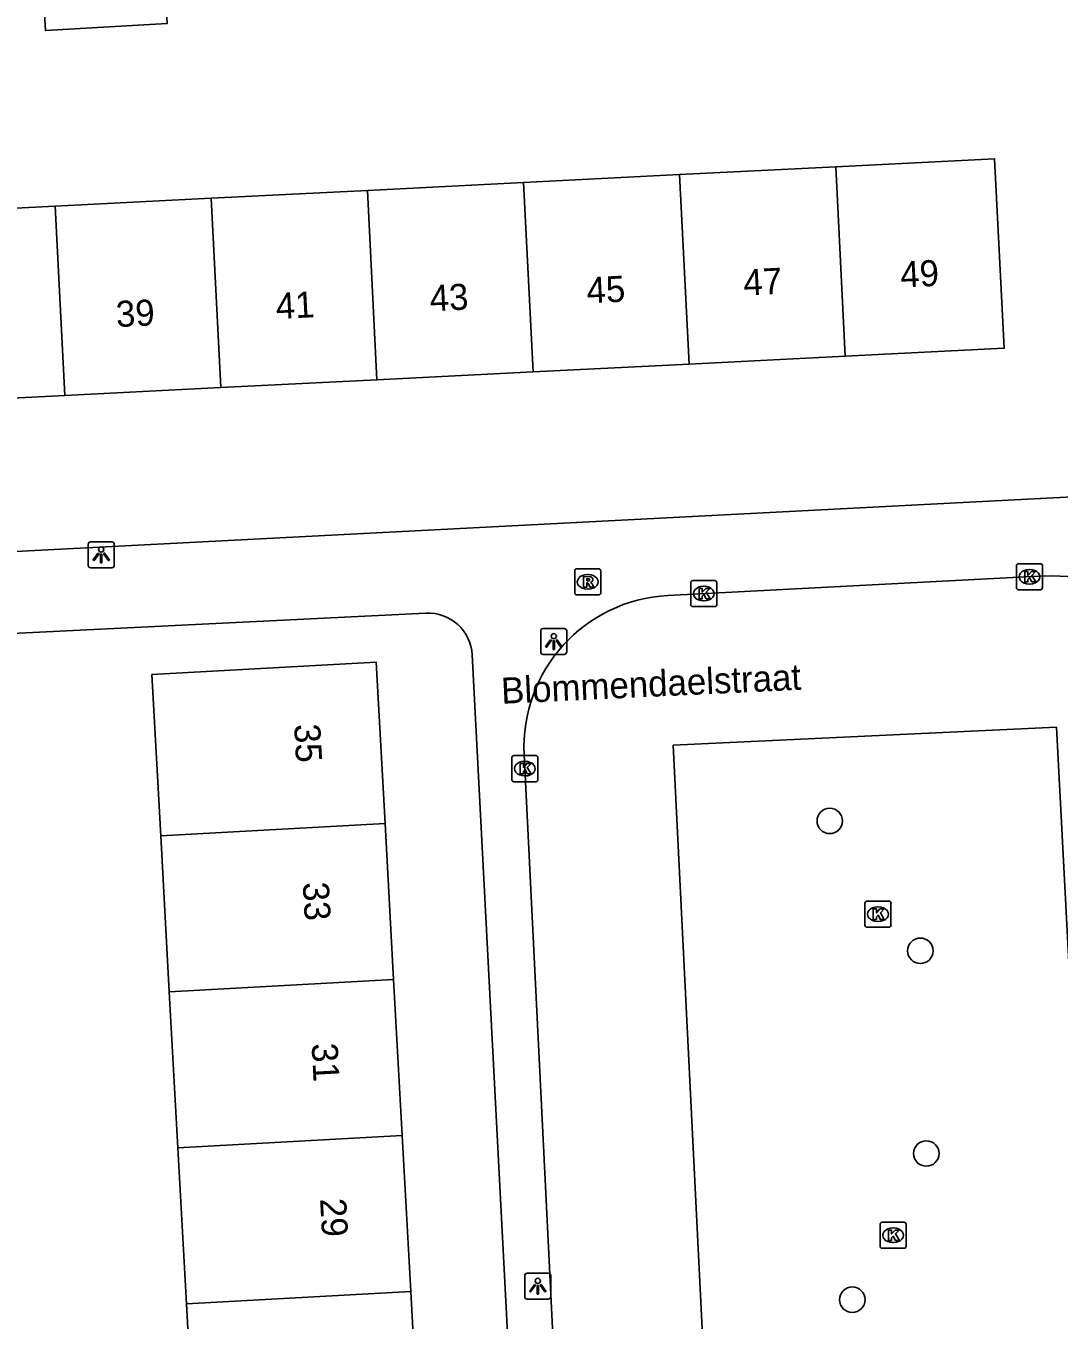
# Model space of a CAD drawing. Extents: x 160557 to 161245, y 385330 to 386505.
# Drawn here: x 161032.93 to 161072.59, y 385418.6 to 385468.29 of the extents above; entities that cross this region are included whole.
import ezdxf

# ---------------------------------------------------------------- set-up
doc = ezdxf.new("R2010")
doc.units = 0
for name, color, linetype in [('IMGEO_Boom', 7, 'Continuous'), ('IMGEO_Kolk', 7, 'Continuous'), ('IMGEO_Lichtpunt', 7, 'Continuous'), ('IMGEO_Openbare_ruimte_label', 7, 'Continuous'), ('IMGEO_Pand', 7, 'Continuous'), ('IMGEO_Pand_nummerreeks', 7, 'Continuous'), ('IMGEO_Rijbaan_lokaal_open', 7, 'Continuous'), ('IMGEO_Rioolput', 7, 'Continuous'), ('IMGEO_Voetpad_open', 7, 'Continuous')]:
    doc.layers.add(name, color=color, linetype=linetype)

msp = doc.modelspace()

# ---------------------------------------------------------------- linework, layer by layer
at = {"layer": 'IMGEO_Boom'}
for centre in [(161063.785, 385437.768), (161067.263, 385432.783), (161067.492, 385425.001), (161064.651, 385419.387)]:
    msp.add_circle(centre, 0.489, dxfattribs=at)
at = {"layer": 'IMGEO_Kolk'}
for p, q in [((161071.025, 385447.642), (161071.877, 385447.642)), ((161070.95, 385446.716), (161070.95, 385447.568)), ((161071.438, 385447.422), (161071.463, 385447.422)), ((161071.951, 385447.568), (161071.951, 385446.716)), ((161058.45, 385446.069), (161058.45, 385446.921)), ((161058.525, 385446.995), (161059.377, 385446.995)), ((161058.938, 385446.775), (161058.963, 385446.775)), ((161059.451, 385446.921), (161059.451, 385446.069)), ((161071.877, 385446.642), (161071.025, 385446.642)), ((161071.461, 385446.862), (161071.436, 385446.862)), ((161058.961, 385446.215), (161058.936, 385446.215)), ((161059.377, 385445.995), (161058.525, 385445.995)), ((161051.581, 385439.349), (161051.581, 385440.201)), ((161051.656, 385440.275), (161052.508, 385440.275)), ((161052.582, 385440.201), (161052.582, 385439.349)), ((161052.069, 385440.055), (161052.094, 385440.055)), ((161052.508, 385439.275), (161051.656, 385439.275)), ((161052.092, 385439.495), (161052.067, 385439.495)), ((161065.135, 385433.762), (161065.135, 385434.614)), ((161065.21, 385434.688), (161066.062, 385434.688)), ((161065.623, 385434.468), (161065.648, 385434.468)), ((161066.136, 385434.614), (161066.136, 385433.762)), ((161065.646, 385433.908), (161065.621, 385433.908)), ((161066.062, 385433.688), (161065.21, 385433.688)), ((161065.717, 385421.436), (161065.717, 385422.288)), ((161065.792, 385422.362), (161066.644, 385422.362)), ((161066.718, 385422.288), (161066.718, 385421.436)), ((161066.205, 385422.142), (161066.23, 385422.142)), ((161066.644, 385421.362), (161065.792, 385421.362)), ((161066.228, 385421.582), (161066.203, 385421.582))]:
    msp.add_line(p, q, dxfattribs=at)
for points in [[(161071.025, 385447.642), (161071.877, 385447.642)], [(161070.95, 385446.716), (161070.95, 385447.568)], [(161071.271, 385447.342), (161071.394, 385447.342), (161071.394, 385447.191), (161071.524, 385447.342), (161071.688, 385447.342), (161071.542, 385447.191), (161071.695, 385446.942), (161071.543, 385446.942), (161071.458, 385447.106), (161071.394, 385447.039), (161071.394, 385446.942), (161071.271, 385446.942), (161071.271, 385447.342)], [(161071.951, 385447.568), (161071.951, 385446.716)], [(161058.45, 385446.069), (161058.45, 385446.921)], [(161058.525, 385446.995), (161059.377, 385446.995)], [(161058.771, 385446.695), (161058.894, 385446.695), (161058.894, 385446.544), (161059.024, 385446.695), (161059.188, 385446.695), (161059.042, 385446.544), (161059.195, 385446.295), (161059.043, 385446.295), (161058.958, 385446.459), (161058.894, 385446.392), (161058.894, 385446.295), (161058.771, 385446.295), (161058.771, 385446.695)], [(161059.451, 385446.921), (161059.451, 385446.069)], [(161071.877, 385446.642), (161071.025, 385446.642)], [(161059.377, 385445.995), (161058.525, 385445.995)], [(161051.581, 385439.349), (161051.581, 385440.201)], [(161051.656, 385440.275), (161052.508, 385440.275)], [(161052.582, 385440.201), (161052.582, 385439.349)], [(161051.902, 385439.975), (161052.025, 385439.975), (161052.025, 385439.824), (161052.155, 385439.975), (161052.319, 385439.975), (161052.173, 385439.824), (161052.326, 385439.575), (161052.174, 385439.575), (161052.089, 385439.739), (161052.025, 385439.672), (161052.025, 385439.575), (161051.902, 385439.575), (161051.902, 385439.975)], [(161052.508, 385439.275), (161051.656, 385439.275)], [(161065.135, 385433.762), (161065.135, 385434.614)], [(161065.21, 385434.688), (161066.062, 385434.688)], [(161065.456, 385434.388), (161065.579, 385434.388), (161065.579, 385434.237), (161065.709, 385434.388), (161065.873, 385434.388), (161065.727, 385434.237), (161065.88, 385433.988), (161065.728, 385433.988), (161065.643, 385434.152), (161065.579, 385434.085), (161065.579, 385433.988), (161065.456, 385433.988), (161065.456, 385434.388)], [(161066.136, 385434.614), (161066.136, 385433.762)], [(161066.062, 385433.688), (161065.21, 385433.688)], [(161065.717, 385421.436), (161065.717, 385422.288)], [(161065.792, 385422.362), (161066.644, 385422.362)], [(161066.718, 385422.288), (161066.718, 385421.436)], [(161066.038, 385422.062), (161066.161, 385422.062), (161066.161, 385421.911), (161066.291, 385422.062), (161066.455, 385422.062), (161066.309, 385421.911), (161066.462, 385421.662), (161066.31, 385421.662), (161066.225, 385421.826), (161066.161, 385421.759), (161066.161, 385421.662), (161066.038, 385421.662), (161066.038, 385422.062)], [(161066.644, 385421.362), (161065.792, 385421.362)]]:
    msp.add_lwpolyline(points, dxfattribs=at)
for centre, start, end in [((161071.027, 385447.566), 91.552, 178.448), ((161071.027, 385447.566), 91.552, 178.448), ((161071.875, 385447.566), 1.552, 88.448), ((161071.875, 385447.566), 1.552, 88.448), ((161058.527, 385446.919), 91.552, 178.448), ((161058.527, 385446.919), 91.552, 178.448), ((161059.375, 385446.919), 1.552, 88.448), ((161059.375, 385446.919), 1.552, 88.448), ((161071.027, 385446.718), 181.552, 268.448), ((161071.027, 385446.718), 181.552, 268.448), ((161071.875, 385446.718), 271.552, 358.448), ((161071.875, 385446.718), 271.552, 358.448), ((161058.527, 385446.071), 181.552, 268.448), ((161058.527, 385446.071), 181.552, 268.448), ((161059.375, 385446.071), 271.552, 358.448), ((161059.375, 385446.071), 271.552, 358.448), ((161051.658, 385440.199), 91.552, 178.448), ((161051.658, 385440.199), 91.552, 178.448), ((161052.506, 385440.199), 1.552, 88.448), ((161052.506, 385440.199), 1.552, 88.448), ((161051.658, 385439.351), 181.552, 268.448), ((161051.658, 385439.351), 181.552, 268.448), ((161052.506, 385439.351), 271.552, 358.448), ((161052.506, 385439.351), 271.552, 358.448), ((161065.212, 385434.612), 91.552, 178.448), ((161065.212, 385434.612), 91.552, 178.448), ((161066.06, 385434.612), 1.552, 88.448), ((161066.06, 385434.612), 1.552, 88.448), ((161065.212, 385433.764), 181.552, 268.448), ((161065.212, 385433.764), 181.552, 268.448), ((161066.06, 385433.764), 271.552, 358.448), ((161066.06, 385433.764), 271.552, 358.448), ((161065.794, 385422.286), 91.552, 178.448), ((161065.794, 385422.286), 91.552, 178.448), ((161066.642, 385422.286), 1.552, 88.448), ((161066.642, 385422.286), 1.552, 88.448), ((161065.794, 385421.438), 181.552, 268.448), ((161065.794, 385421.438), 181.552, 268.448), ((161066.642, 385421.438), 271.552, 358.448), ((161066.642, 385421.438), 271.552, 358.448)]:
    msp.add_arc(centre, 0.0765, start, end, dxfattribs=at)
for centre, major_axis, ratio, start_param, end_param in [((161071.437, 385447.142), (-0.387, 0.002), 0.722429, 4.712389, 7.853982), ((161071.462, 385447.142), (-0.39, 0.002), 0.717154, 1.570796, 4.712389), ((161058.937, 385446.495), (-0.387, 0.002), 0.722429, 4.712389, 7.853982), ((161058.962, 385446.495), (-0.39, 0.002), 0.717154, 1.570796, 4.712389), ((161052.068, 385439.775), (-0.387, 0.002), 0.722429, 4.712389, 7.853982), ((161052.093, 385439.775), (-0.39, 0.002), 0.717154, 1.570796, 4.712389), ((161065.622, 385434.188), (-0.387, 0.002), 0.722429, 4.712389, 7.853982), ((161065.647, 385434.188), (-0.39, 0.002), 0.717154, 1.570796, 4.712389), ((161066.204, 385421.862), (-0.387, 0.002), 0.722429, 4.712389, 7.853982), ((161066.229, 385421.862), (-0.39, 0.002), 0.717154, 1.570796, 4.712389)]:
    msp.add_ellipse(centre, major_axis=major_axis, ratio=ratio, start_param=start_param, end_param=end_param, dxfattribs=at)
at = {"layer": 'IMGEO_Lichtpunt'}
for p, q in [((161035.323, 385448.387), (161035.323, 385447.58)), ((161035.323, 385448.387), (161035.323, 385447.58)), ((161036.225, 385448.482), (161035.417, 385448.482)), ((161036.225, 385448.482), (161035.417, 385448.482)), ((161036.319, 385447.58), (161036.319, 385448.387)), ((161036.319, 385447.58), (161036.319, 385448.387)), ((161035.417, 385447.486), (161036.225, 385447.486)), ((161035.417, 385447.486), (161036.225, 385447.486)), ((161053.594, 385445.156), (161052.786, 385445.156)), ((161053.594, 385445.156), (161052.786, 385445.156)), ((161052.692, 385445.061), (161052.692, 385444.254)), ((161052.692, 385445.061), (161052.692, 385444.254)), ((161053.688, 385444.254), (161053.688, 385445.061)), ((161053.688, 385444.254), (161053.688, 385445.061)), ((161052.786, 385444.16), (161053.594, 385444.16)), ((161052.786, 385444.16), (161053.594, 385444.16)), ((161052.08, 385420.312), (161052.08, 385419.505)), ((161052.08, 385420.312), (161052.08, 385419.505)), ((161052.982, 385420.407), (161052.174, 385420.407)), ((161052.982, 385420.407), (161052.174, 385420.407)), ((161053.076, 385419.505), (161053.076, 385420.312)), ((161053.076, 385419.505), (161053.076, 385420.312)), ((161052.174, 385419.411), (161052.982, 385419.411)), ((161052.174, 385419.411), (161052.982, 385419.411))]:
    msp.add_line(p, q, dxfattribs=at)
for points in [[(161035.697, 385448.051), (161035.736, 385448.023), (161035.548, 385447.761), (161035.51, 385447.788), (161035.697, 385448.051)], [(161035.799, 385448.003), (161035.846, 385448.003), (161035.846, 385447.681), (161035.799, 385447.681), (161035.799, 385448.003)], [(161035.909, 385448.023), (161035.947, 385448.05), (161036.134, 385447.788), (161036.095, 385447.76), (161035.909, 385448.023)], [(161053.066, 385444.725), (161053.105, 385444.697), (161052.917, 385444.435), (161052.879, 385444.462), (161053.066, 385444.725)], [(161053.168, 385444.677), (161053.215, 385444.677), (161053.215, 385444.355), (161053.168, 385444.355), (161053.168, 385444.677)], [(161053.278, 385444.697), (161053.316, 385444.724), (161053.503, 385444.462), (161053.464, 385444.434), (161053.278, 385444.697)], [(161052.454, 385419.976), (161052.493, 385419.948), (161052.305, 385419.686), (161052.267, 385419.713), (161052.454, 385419.976)], [(161052.556, 385419.928), (161052.603, 385419.928), (161052.603, 385419.606), (161052.556, 385419.606), (161052.556, 385419.928)], [(161052.666, 385419.948), (161052.704, 385419.975), (161052.891, 385419.713), (161052.852, 385419.685), (161052.666, 385419.948)]]:
    msp.add_lwpolyline(points, dxfattribs=at)
for centre in [(161035.822, 385448.185), (161053.191, 385444.859), (161052.579, 385420.11)]:
    msp.add_circle(centre, 0.0994, dxfattribs=at)
for centre, start, end in [((161035.417, 385448.387), 90, 180), ((161035.417, 385448.387), 90, 180), ((161036.225, 385448.387), 0, 90), ((161036.225, 385448.387), 0, 90), ((161035.417, 385447.58), 180, 270), ((161035.417, 385447.58), 180, 270), ((161036.225, 385447.58), 270, 0), ((161036.225, 385447.58), 270, 360), ((161052.786, 385445.061), 90, 180), ((161052.786, 385445.061), 90, 180), ((161053.594, 385445.061), 0, 90), ((161053.594, 385445.061), 0, 90), ((161052.786, 385444.254), 180, 270), ((161052.786, 385444.254), 180, 270), ((161053.594, 385444.254), 270, 0), ((161053.594, 385444.254), 270, 360), ((161052.174, 385420.312), 90, 180), ((161052.174, 385420.312), 90, 180), ((161052.982, 385420.312), 0, 90), ((161052.982, 385420.312), 0, 90), ((161052.174, 385419.505), 180, 270), ((161052.174, 385419.505), 180, 270), ((161052.982, 385419.505), 270, 0), ((161052.982, 385419.505), 270, 360)]:
    msp.add_arc(centre, 0.0946, start, end, dxfattribs=at)
at = {"layer": 'IMGEO_Pand'}
for points in [[(161038.209, 385470.94), (161038.357, 385468.383), (161033.677, 385468.112), (161033.529, 385470.669)], [(161064.382, 385455.609), (161070.476, 385455.916), (161070.11, 385463.187), (161064.016, 385462.88)], [(161052.032, 385462.276), (161058.024, 385462.578)], [(161064.016, 385462.88), (161058.024, 385462.578)], [(161058.024, 385462.578), (161058.39, 385455.307)], [(161064.016, 385462.88), (161064.382, 385455.609)], [(161052.032, 385462.276), (161046.039, 385461.974)], [(161052.398, 385455.005), (161052.032, 385462.276)], [(161040.047, 385461.673), (161034.054, 385461.371)], [(161040.047, 385461.673), (161046.039, 385461.974)], [(161040.413, 385454.402), (161040.047, 385461.673)], [(161046.039, 385461.974), (161046.405, 385454.703)], [(161034.054, 385461.371), (161027.965, 385461.064)], [(161034.42, 385454.1), (161034.054, 385461.371)], [(161058.39, 385455.307), (161064.382, 385455.609)], [(161058.39, 385455.307), (161052.398, 385455.005)], [(161046.405, 385454.703), (161040.413, 385454.402)], [(161046.405, 385454.703), (161052.398, 385455.005)], [(161028.331, 385453.793), (161034.42, 385454.1)], [(161034.42, 385454.1), (161040.413, 385454.402)], [(161038.107, 385437.2), (161037.768, 385443.389), (161046.378, 385443.86), (161046.716, 385437.671)], [(161038.107, 385437.2), (161046.716, 385437.671)], [(161038.434, 385431.209), (161038.107, 385437.2)], [(161046.716, 385437.671), (161047.044, 385431.68)], [(161038.434, 385431.209), (161047.044, 385431.68)], [(161047.044, 385431.68), (161047.372, 385425.688)], [(161038.762, 385425.217), (161038.434, 385431.209)], [(161047.372, 385425.688), (161038.762, 385425.217)], [(161047.372, 385425.688), (161047.7, 385419.697)], [(161039.09, 385419.226), (161038.762, 385425.217)], [(161047.7, 385419.697), (161048.038, 385413.509), (161039.428, 385413.039), (161039.09, 385419.226)], [(161039.09, 385419.226), (161047.7, 385419.697)]]:
    msp.add_lwpolyline(points, dxfattribs=at)
at = {"layer": 'IMGEO_Rijbaan_lokaal_open'}
for points in [[(161057.575, 385446.422), (161072.038, 385447.171)], [(161072.491, 385441.37), (161057.78, 385440.68), (161059.018, 385415.696), (161073.778, 385416.7), (161072.491, 385441.37)], [(161053.28, 385415.442), (161052.056, 385440.315)]]:
    msp.add_lwpolyline(points, dxfattribs=at)
for centre, radius, start, end in [((161072.311, 385441.408), 5.769, 3.2282, 92.7104), ((161057.876, 385440.603), 5.827, 92.9602, 182.8305)]:
    msp.add_arc(centre, radius, start, end, dxfattribs=at)
at = {"layer": 'IMGEO_Rioolput'}
for p, q in [((161053.996, 385446.52), (161053.996, 385447.372)), ((161054.071, 385447.446), (161054.923, 385447.446)), ((161054.484, 385447.226), (161054.509, 385447.226)), ((161054.997, 385447.372), (161054.997, 385446.52)), ((161054.507, 385446.666), (161054.482, 385446.666)), ((161054.923, 385446.446), (161054.071, 385446.446))]:
    msp.add_line(p, q, dxfattribs=at)
for points in [[(161053.996, 385446.52), (161053.996, 385447.372)], [(161054.071, 385447.446), (161054.923, 385447.446)], [(161054.585, 385447.144), (161054.333, 385447.146), (161054.333, 385446.746)], [(161054.997, 385447.372), (161054.997, 385446.52)], [(161054.333, 385446.746), (161054.457, 385446.746), (161054.457, 385446.908), (161054.468, 385446.908)], [(161054.511, 385447.065), (161054.457, 385447.065), (161054.457, 385446.984)], [(161054.457, 385446.984), (161054.509, 385446.984)], [(161054.515, 385446.879), (161054.586, 385446.746), (161054.726, 385446.746), (161054.661, 385446.872)], [(161054.923, 385446.446), (161054.071, 385446.446)]]:
    msp.add_lwpolyline(points, dxfattribs=at)
for centre, radius, start, end in [((161054.073, 385447.37), 0.0765, 91.552, 178.448), ((161054.073, 385447.37), 0.0765, 91.552, 178.448), ((161054.584, 385447.034), 0.109, 350.3612, 89.416), ((161054.921, 385447.37), 0.0765, 1.552, 88.448), ((161054.921, 385447.37), 0.0765, 1.552, 88.448), ((161054.467, 385446.855), 0.0533, 26.0293, 88.6989), ((161054.493, 385447.173), 0.19, 274.7715, 282.9687), ((161054.517, 385446.969), 0.0964, 77.0061, 93.1865), ((161054.531, 385447.026), 0.0378, 276.6634, 79.6772), ((161054.582, 385447.034), 0.112, 277.5842, 350.9817), ((161054.566, 385446.819), 0.108, 29.5134, 73.7905), ((161054.073, 385446.522), 0.0765, 181.552, 268.448), ((161054.073, 385446.522), 0.0765, 181.552, 268.448), ((161054.921, 385446.522), 0.0765, 271.552, 358.448), ((161054.921, 385446.522), 0.0765, 271.552, 358.448)]:
    msp.add_arc(centre, radius, start, end, dxfattribs=at)
for centre, major_axis, ratio, start_param, end_param in [((161054.483, 385446.946), (-0.387, 0.002), 0.722429, 4.712389, 7.853982), ((161054.508, 385446.946), (-0.39, 0.002), 0.717154, 1.570796, 4.712389)]:
    msp.add_ellipse(centre, major_axis=major_axis, ratio=ratio, start_param=start_param, end_param=end_param, dxfattribs=at)
at = {"layer": 'IMGEO_Voetpad_open'}
for points in [[(161074.342, 385450.271), (161028.558, 385447.91)], [(161048.287, 385445.743), (161028.752, 385444.779)], [(161051.668, 385413.192), (161050.066, 385444.139)]]:
    msp.add_lwpolyline(points, dxfattribs=at)
msp.add_arc((161048.371, 385444.048), 1.697, 3.087, 92.8354, dxfattribs=at)

# ---------------------------------------------------------------- texts
at = {"layer": 'IMGEO_Openbare_ruimte_label'}
msp.add_text('Blommendaelstraat', height=1, rotation=2.6936, dxfattribs=at).set_placement((161051.194, 385442.265))
at = {"layer": 'IMGEO_Pand_nummerreeks'}
for s, rotation, p in [('49', 2.8838, (161066.514, 385458.24)), ('45', 2.8838, (161054.472, 385457.633)), ('47', 2.8838, (161060.493, 385457.936)), ('41', 2.8838, (161042.544, 385457.032)), ('43', 2.8838, (161048.452, 385457.33)), ('39', 2.8838, (161036.41, 385456.723)), ('35', 273.1306, (161043.224, 385441.471)), ('33', 273.1306, (161043.556, 385435.4)), ('31', 273.1306, (161043.894, 385429.218)), ('29', 273.1306, (161044.22, 385423.26))]:
    msp.add_text(s, height=1, rotation=rotation, dxfattribs=at).set_placement(p)

doc.saveas('drawing.dxf')
